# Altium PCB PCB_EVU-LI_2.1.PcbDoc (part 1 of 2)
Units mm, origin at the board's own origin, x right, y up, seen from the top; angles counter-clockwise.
Board outline 33.02 x 17.78 mm, 4 copper layers (Top, Int_1, Int_2, Bot), stack 1.546 mm thick; 75 components, 60 nets, 297 pads, 132 vias.
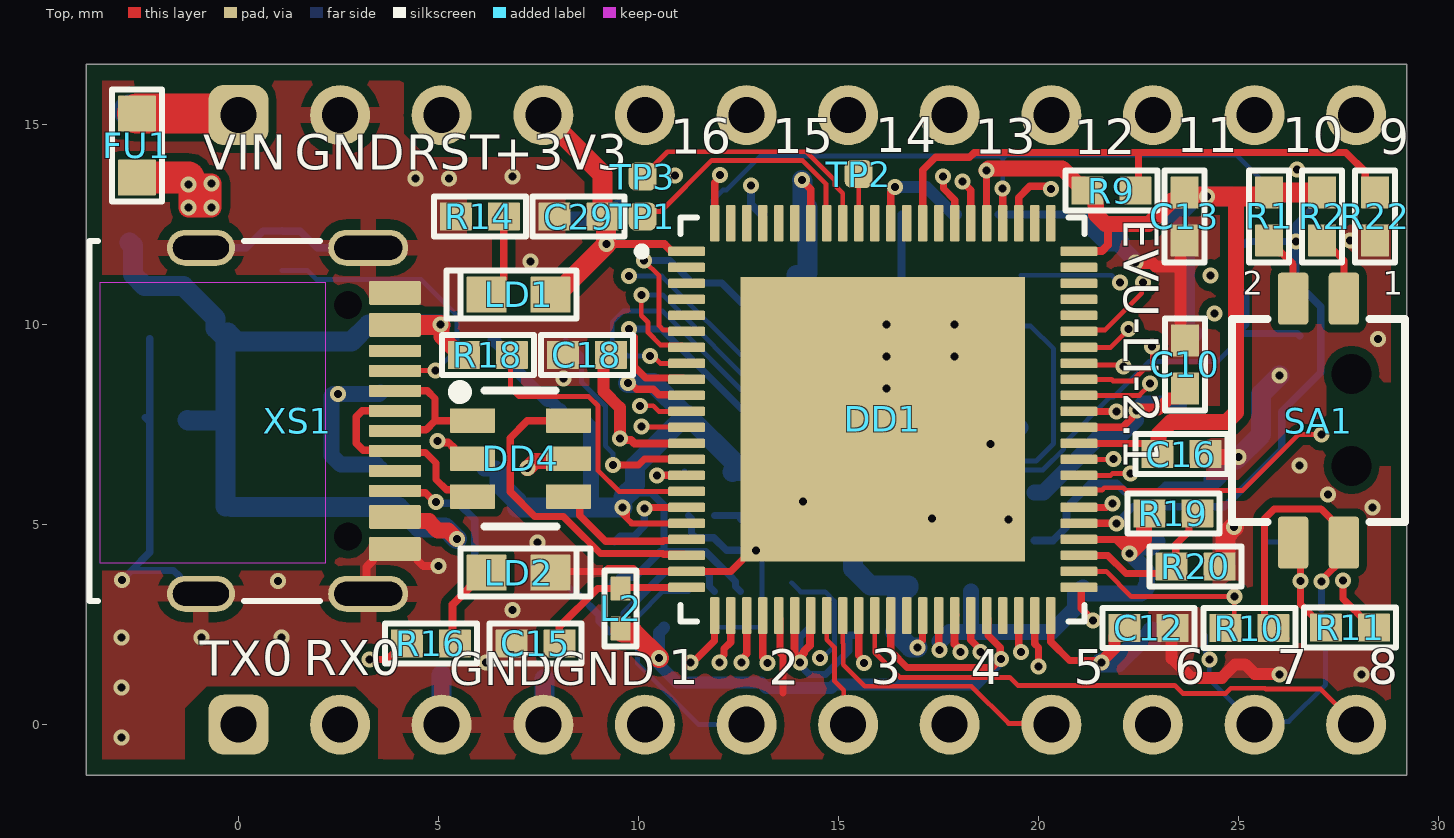
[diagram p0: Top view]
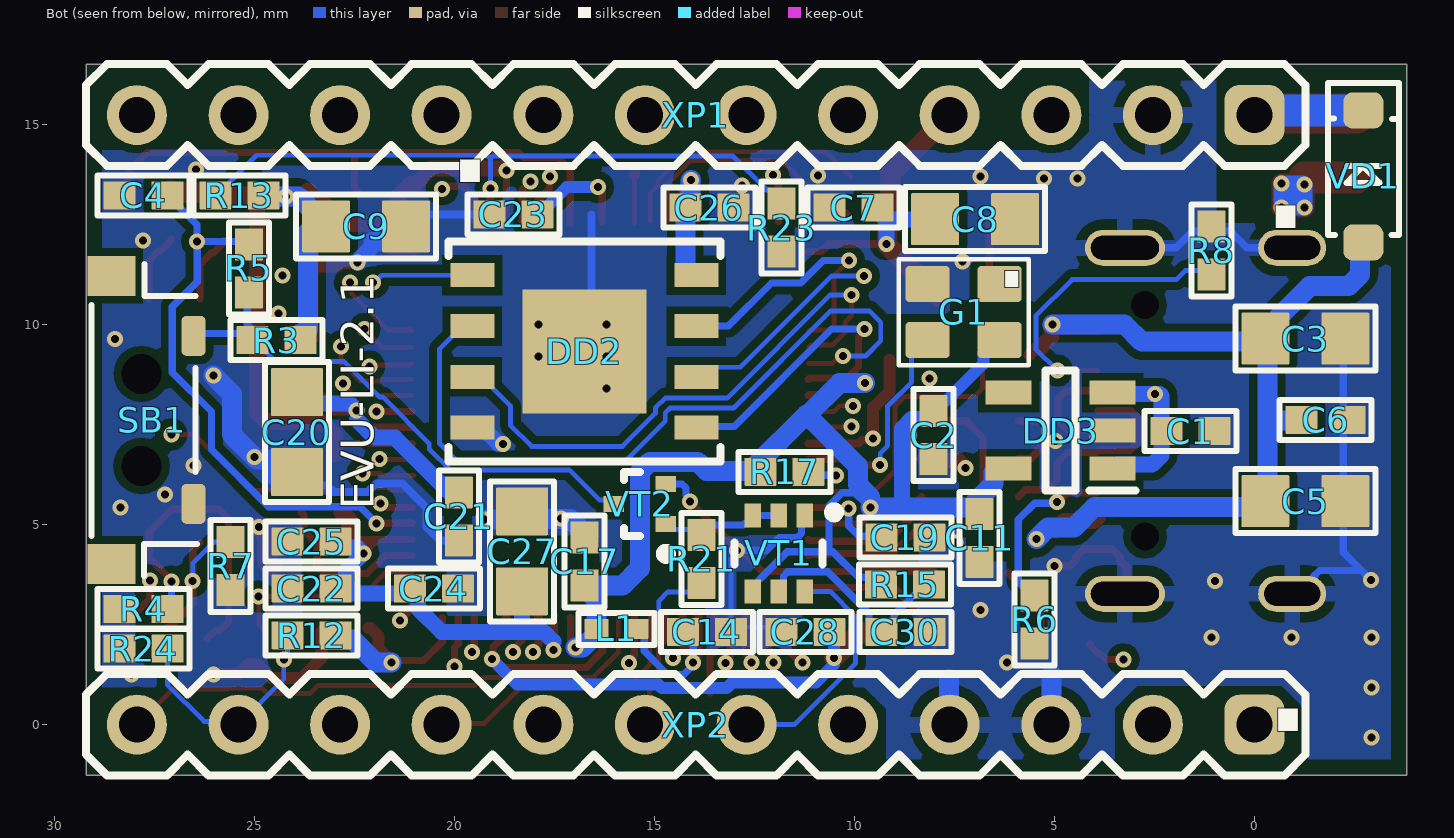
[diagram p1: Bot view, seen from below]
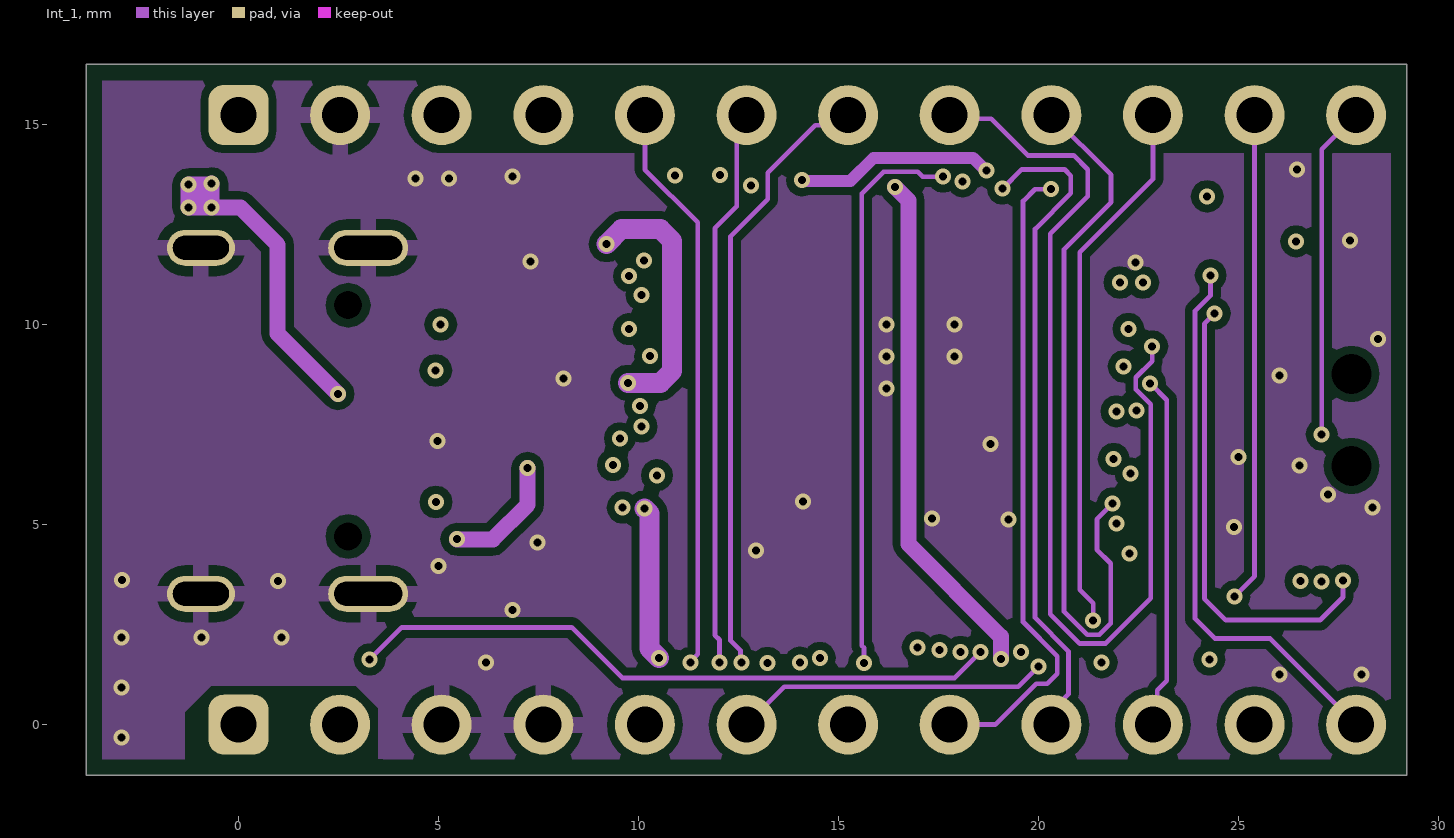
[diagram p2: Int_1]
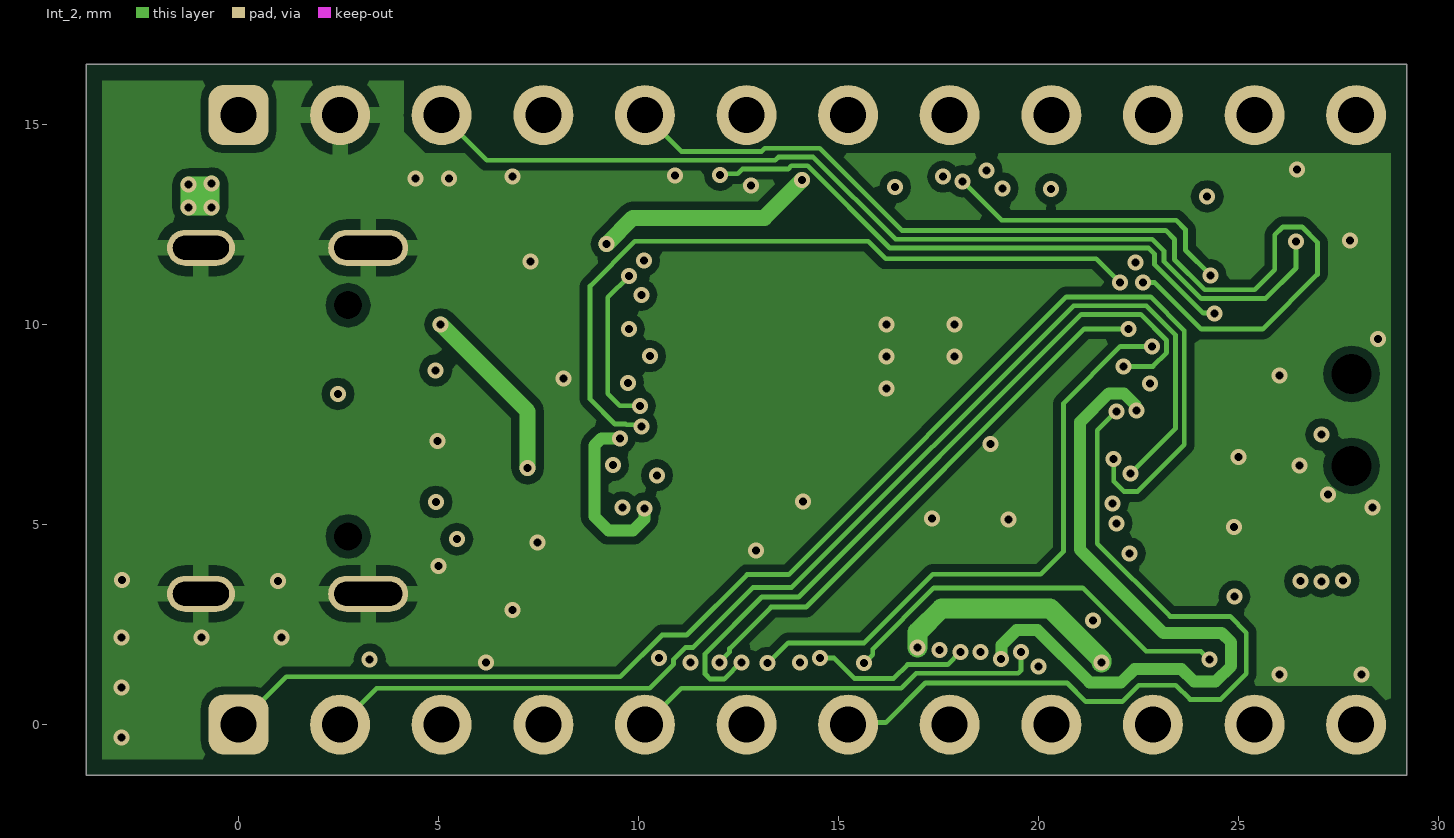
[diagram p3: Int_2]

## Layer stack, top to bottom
Top Solder: solder mask 0.01, Solder Resist, Dk 3.5
Top: signal copper 0.035
Prepreg_T: prepreg 0.138, TG-150, Dk 4.2
Int_1: signal copper 0.018
Core: core 1.164, TG-150, Dk 4.6
Int_2: signal copper 0.018
Prepreg_B: prepreg 0.138, TG-150, Dk 4.2
Bot: signal copper 0.035
Bottom Solder: solder mask 0.01, Solder Resist, Dk 3.5

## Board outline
-3.81,-1.27 -3.81,16.51 29.21,16.51 29.21,-1.27

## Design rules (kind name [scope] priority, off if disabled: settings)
AssemblyTestPointUsage [All] p1 off:
AssemblyTestpoint [All] p1 off: testpointundercomponent=TRUE minsize=1.016 maxsize=2.54 preferedsize=1.524 minholesize=0 maxholesize=1.016 preferedholesize=0.813 testpointgrid=0.025 usegrid=TRUE gridtolerance=0 allowsidetop=TRUE allowsidebottom=TRUE
BoardOutlineClearance [All] p1: gap=0.4 ignorepadtopadclearanceinfootprint=FALSE except(0: Arc-SplitContinuation Track-SplitContinuation SMDPad-SplitContinuation THPad-SplitContinuation Via-SplitContinuation Fill-SplitContinuation Poly-SplitContinuation Region-SplitContinuation Text-SplitContinuation)
Clearance Clearance_board_edge [OnLayer('Keep-Out Layer')] p1: gap=0.2 ignorepadtopadclearanceinfootprint=FALSE
Clearance Clearance_Poly_to_Poly [InPolygon vs InPolygon] p2: gap=0.4 ignorepadtopadclearanceinfootprint=FALSE except(0: Arc-Hole Track-Hole SMDPad-Hole THPad-Hole Via-Hole Fill-Hole Poly-Hole Region-Hole Text-Hole)
Clearance Clearance_Polygon [InPolygon] p3: gap=0.2 ignorepadtopadclearanceinfootprint=FALSE except(0: Text-Hole)
Clearance Clearance_Int_layer [OnLayer('Int_layer_1') or OnLayer('Int_layer_2')] p4: gap=0.2 ignorepadtopadclearanceinfootprint=FALSE except(0: Text-Hole)
Clearance [All] p5: gap=0.1 ignorepadtopadclearanceinfootprint=FALSE
ComponentClearance [All] p1 off: gap=0 collisioncheckmode=3 verticalgap=1 showdistances=FALSE
DiffPairsRouting DiffPairs_100 [InDifferentialPairClass('100 Ohm')] p1: maxlimit=0.18 minlimit=0.13 mostfreqgap=0.18 toplayer_maxgap=0.13 toplayer_prefgap=0.13 toplayer_minwidth=0.14 toplayer_maxwidth=0.14 toplayer_prefwidth=0.14 bottomlayer_maxgap=0.13 bottomlayer_prefgap=0.13 bottomlayer_minwidth=0.14 bottomlayer_maxwidth=0.14 bottomlayer_prefwidth=0.14 impedanceprofiledriven=TRUE impedanceprofileid={9381E8F4-4B66-44EE-9FF4-B1D978838FA6} impedanceprofilevalue=100.000000 maxuncoupledlength=12.7
DiffPairsRouting DiffPair_90 [InDifferentialPairClass('90 Ohm')] p2: maxlimit=0.13 minlimit=0.13 mostfreqgap=0.13 toplayer_minwidth=0.18 toplayer_maxwidth=0.18 toplayer_prefwidth=0.18 midlayer1_minwidth=0.11 midlayer1_maxwidth=0.11 midlayer1_prefwidth=0.11 midlayer2_minwidth=0.11 midlayer2_maxwidth=0.11 midlayer2_prefwidth=0.11 bottomlayer_minwidth=0.18 bottomlayer_maxwidth=0.18 bottomlayer_prefwidth=0.18 impedanceprofiledriven=TRUE impedanceprofileid={33ED77F1-C44D-40A2-8D01-BA86BD42C323} impedanceprofilevalue=90.000000 maxuncoupledlength=12.7
DiffPairsRouting [All] p3: maxlimit=0.25 minlimit=0.15 mostfreqgap=0.25 toplayer_maxgap=0.15 toplayer_prefgap=0.15 toplayer_minwidth=0.15 toplayer_maxwidth=0.3 toplayer_prefwidth=0.3 midlayer1_mingap=0.2 midlayer1_minwidth=0.2 midlayer1_maxwidth=0.2 midlayer1_prefwidth=0.2 midlayer2_mingap=0.25 midlayer2_minwidth=0.25 midlayer2_maxwidth=0.25 midlayer2_prefwidth=0.25 bottomlayer_maxgap=0.15 bottomlayer_prefgap=0.15 bottomlayer_minwidth=0.15 bottomlayer_maxwidth=0.3 bottomlayer_prefwidth=0.3 maxuncoupledlength=12.7
FabricationTestPointUsage [All] p1 off: valid=0 allowmultiple=FALSE
FabricationTestpoint [All] p1 off: side=3 testpointundercomponent=TRUE minsize=1.016 maxsize=2.54 preferedsize=1.524 minholesize=0 maxholesize=1.016 preferedholesize=0.813 testpointgrid=0.025 allowsidetop=TRUE allowsidebottom=TRUE usegrid=TRUE gridtolerance=0
FanoutControl Fanout_BGA [IsBGA] p1 off: bgadir=Out bgaviamode=Centered fanoutstyle=Auto fanoutdirection=Alternating viagrid=0.025 // Fanout_BGA (Default Rule)
FanoutControl Fanout_LCC [IsLCC] p2 off: bgadir=Out bgaviamode=Centered fanoutstyle=Auto fanoutdirection=Alternating viagrid=0.025 // Fanout_LCC (Default Rule)
FanoutControl Fanout_SOIC [IsSOIC] p3 off: bgadir=Out bgaviamode=Centered fanoutstyle=Auto fanoutdirection=Alternating viagrid=0.025 // Fanout_SOIC (Default Rule)
FanoutControl Fanout_Small [(CompPinCount < 5)] p4 off: bgadir=Out bgaviamode=Centered fanoutstyle=Auto fanoutdirection=OutThenIn viagrid=0.025 // Fanout_Small (Default Rule)
FanoutControl Fanout_Default [All] p5 off: bgadir=Out bgaviamode=Centered fanoutstyle=Auto fanoutdirection=Alternating viagrid=0.025 // Fanout_Default (Default Rule)
Height [All] p1 off: minheight=0.2 maxheight=16 prefheight=16
HoleSize [All] p1 off: absolutevalues=TRUE maxlimit=9 minlimit=0.3 maxpercent=80.000 minpercent=20.000
HoleToHoleClearance [All] p1: gap=0.5 allowstackedmicrovias=TRUE
Length [InNetClass('CSI')] p1: maxlimit=24.1 minlimit=22.1
MatchedLengths USB1c [InNetClass('USB1_c')] p1: tolerance=25.4 checknetsindiffpair=FALSE checkdiffpairvsdiffpair=TRUE checkxsignals=TRUE checkothers=TRUE usedelayunits=TRUE delaytolerance=10.000000
MatchedLengths USB0c [InNetClass('USB0_c')] p2: tolerance=25.4 checknetsindiffpair=FALSE checkdiffpairvsdiffpair=TRUE checkxsignals=TRUE checkothers=TRUE usedelayunits=TRUE delaytolerance=10.000000
MatchedLengths I2S1 [InxSignalClass('I2S1')] p3: tolerance=25.4 checknetsindiffpair=FALSE checkdiffpairvsdiffpair=TRUE checkxsignals=TRUE checkothers=TRUE usedelayunits=TRUE delaytolerance=10.000000
MatchedLengths I2S0 [InxSignalClass('I2S0')] p4: tolerance=25.4 checknetsindiffpair=FALSE checkdiffpairvsdiffpair=TRUE checkxsignals=TRUE checkothers=TRUE usedelayunits=TRUE delaytolerance=10.000000
MatchedLengths DP [InxSignalClass('DP')] p5: tolerance=25.4 checknetsindiffpair=FALSE checkdiffpairvsdiffpair=TRUE checkxsignals=TRUE checkothers=TRUE usedelayunits=TRUE delaytolerance=10.000000
MatchedLengths USB1 [InxSignalClass('USB1')] p6: tolerance=25.4 checknetsindiffpair=FALSE checkdiffpairvsdiffpair=TRUE checkxsignals=TRUE checkothers=TRUE usedelayunits=TRUE delaytolerance=10.000000
MatchedLengths USB0 [InxSignalClass('USB0')] p7: tolerance=25.4 checknetsindiffpair=FALSE checkdiffpairvsdiffpair=TRUE checkxsignals=TRUE checkothers=TRUE usedelayunits=TRUE delaytolerance=10.000000
MinimumSolderMaskSliver MinimumSolderMaskSliver_TQFP [InComponentClass('TQFP_MSK_SL_0.1')] p1: minsoldermaskwidth=0.1
MinimumSolderMaskSliver [All] p2: minsoldermaskwidth=0.15
PlaneClearance [All] p1: clearance=0.4
PlaneConnect PlaneConnect_Direct [InComponentClass('Mount_DirConn')] p1: planeconnectstyle=Direct reliefexpansion=0.508 reliefentries=4 reliefconductorwidth=0.254 reliefairgap=0.254
PlaneConnect PlaneConnect_VIA [IsVia] p2: planeconnectstyle=Direct reliefexpansion=0.508 reliefentries=4 reliefconductorwidth=0.254 reliefairgap=0.254
PlaneConnect [All] p3: planeconnectstyle=Relief reliefexpansion=0.3 reliefentries=4 reliefconductorwidth=0.5 reliefairgap=0.3
PolygonConnect PolygonConnect_DIRECT [IsPadHoleValid vs IsPolygon] p1: connectstyle=Relief reliefconductorwidth=0.4 reliefentries=4 polygonreliefangle="90 Angle" airgapwidth=0.254
PolygonConnect PolygonCON_VIA [IsVia vs IsPolygon] p2: connectstyle=Direct reliefconductorwidth=0.254 reliefentries=4 polygonreliefangle="90 Angle" airgapwidth=0.254
PolygonConnect [All] p3: connectstyle=Direct reliefconductorwidth=0.5 reliefentries=4 polygonreliefangle="90 Angle" airgapwidth=0.2
RoutingCorners [All] p1: cornerstyle=45-Degree minsetback=2.5 maxsetback=2.5
RoutingVias [All] p1: holewidth=0.3 width=0.7 viastyle="Through Hole" minholewidth=0.2 minwidth=0.4 maxholewidth=0.5 maxwidth=1.2
SilkToSilkClearance [All] p1 off: silktosilkclearance=0
SilkToSolderMaskClearance SilkscreenOverComponentPads [IsPad] p1 off: minsilkscreentomaskgap=0.2 clearancetoexposedcopper=TRUE
SolderMaskExpansion SolderMaskExpansion_via [IsVia] p1: expansion=-0.8 istentingtop=FALSE
SolderMaskExpansion [All] p2: expansion=0.075 istentingtop=FALSE
Width Width_50 [InNetClass('S50')] p1: maxlimit=0.2 minlimit=0.14 preferedwidth=0.2 toplayer_minwidth=0.2 bottomlayer_minwidth=0.2 impedanceprofiledriven=TRUE impedanceprofileid={09F03C0F-4992-4264-92D2-5678F8C1E202} impedanceprofilevalue=50.000000 minimp=50.000000 maximp=50.000000 favimp=50.000000
Width Width_PWR [InNetClass('PWR')] p2: maxlimit=2 minlimit=0.2 preferedwidth=0.7 midlayer2_maxwidth=1.5 minimp=50.000000 maximp=50.000000 favimp=50.000000
Width [All] p3: maxlimit=1 minlimit=0.12 preferedwidth=0.3 minimp=50.000000 maximp=50.000000 favimp=50.000000
10 further rules are at their usual default settings.

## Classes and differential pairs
differential pair class "90 Ohm": USB
differential pair USB: +USB_p -USB_n

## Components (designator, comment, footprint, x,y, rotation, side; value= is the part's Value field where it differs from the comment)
C1 "GRM155R71C104KA88D" CAPC1005X50N 1.605,7.337 r0 bottom value=100nF
C2 "GRM155R71C104KA88D" CAPC1005X50N 8.021,7.235 r90 bottom value=100nF
C3 "GRM21BR61C106KE15L" CAPC2012X125N -1.27,9.652 r0 bottom value=10uF
C4 "GRM155R71C104KA88D" CAPC1005X50N 27.777,13.234 r180 bottom value=100nF
C5 "GRM21BR61C106KE15L" CAPC2012X125N -1.27,5.588 r0 bottom value=10uF
C6 "GRM155R71C104KA88D" CAPC1005X50N -1.778,7.62 r0 bottom value=100nF
C7 "GRM155R71C104KA88D" CAPC1005X50N 10.022,12.928 r180 bottom value=100nF
C8 "GRM21BR61C106KE15L" CAPC2012X125N 6.984,12.637 r0 bottom value=10uF
C9 "GRM21BR61C106KE15L" CAPC2012X125N 22.212,12.458 r0 bottom value=10uF
C10 "GRM155R71C104KA88D" CAPC1005X50N 23.668,9.004 r270 top value=100nF
C11 "GRM155R71C104KA88D" CAPC1005X50N 6.87,4.672 r90 bottom value=100nF
C12 "GRM155R71C104KA88D" CAPC1005X50N 22.754,2.422 r180 top value=100nF
C13 "GRM155R71C104KA88D" CAPC1005X50N 23.655,12.705 r90 top value=100nF
C14 "GRM155R71C104KA88D" CAPC1005X50N 13.69,2.32 r0 bottom value=100nF
C15 "GRM155R71C104KA88D" CAPC1005X50N 7.43,2.029 r0 top value=100nF
C16 "GRM155R71C104KA88D" CAPC1005X50N 23.57,6.764 r180 top value=100nF
C17 "GRM155R71C104KA88D" CAPC1005X50N 16.747,4.079 r270 bottom value=100nF
C18 "GRM155R71C104KA88D" CAPC1005X50N 8.708,9.244 r0 top value=100nF
C19 "GRM155R71C104KA88D" CAPC1005X50N 8.727,4.68 r0 bottom value=100nF
C20 "GRM21BR61C106KE15L" CAPC2012X125N 23.939,7.316 r90 bottom value=10uF
C21 "GRM155R71C104KA88D" CAPC1005X50N 19.894,5.209 r90 bottom value=100nF
C22 "GRM155R71C104KA88D" CAPC1005X50N 23.571,3.4 r180 bottom value=100nF
C23 "GRM155R71C104KA88D" CAPC1005X50N 18.531,12.754 r180 bottom value=100nF
C24 "GRM155R71C104KA88D" CAPC1005X50N 20.515,3.4 r0 bottom value=100nF
C25 "GRM155R71C104KA88D" CAPC1005X50N 23.571,4.576 r180 bottom value=100nF
C26 "GRM155R71C104KA88D" CAPC1005X50N 13.63,12.928 r0 bottom value=100nF
C27 "GRM21BR61C106KE15L" CAPC2012X125N 18.311,4.332 r270 bottom value=10uF
C28 "GRM155R71C104KA88D" CAPC1005X50N 11.231,2.32 r180 bottom value=100nF
C29 "GRM155R71C104KA88D" CAPC1005X50N 8.5,12.7 r0 top value=100nF
C30 "GRM155Z71A105KE01D" CAPC1005X50N 8.727,2.32 r180 bottom value=1uF
DD1 "BE-U1000" QFNWB10X10-88L-AL 16.105,7.63 r0 top
DD2 "MT25QL128ABA1EW7-0SIT" W-PDFN-8(5x6) 16.755,9.33 r180 bottom
DD3 "AP2112K-3.3TRG1" SOT95P285X140-5N 4.847,7.349 r0 bottom
DD4 "USBLC6-2SC6" SOT95P280X145-6N 7.05,6.65 r0 top
FU1 "JFC0603-0500FS" RESC1608X45N -2.54,14.478 r270 top value=500mA
G1 "OT252025MJBA4SL" Crystal_4-SMD_2.5x2.0 7.274,10.316 r0 bottom
L1 "BLM15AX601SN1" BLM15X10X05X50N 15.955,2.397 r180 bottom value="600 Ом/100MГц 0,5A 0,34 Ом"
L2 "BLM15AX601SN1" BLM15X10X05X50N 9.555,2.905 r90 top value="600 Ом/100MГц 0,5A 0,34 Ом"
LD1 "KPT-1608PWF-A" KPT1608X16X08X75N_LINE 7,10.75 r180 top
LD2 "KPT-1608SGC" KPT1608X16X08X75N_LINE 7,3.8 r0 top
R1 "RC0402FR-071KL" RESC1005X35N 25.767,12.705 r270 top value=1K
R2 "RC0402FR-071KL" RESC1005X35N 27.089,12.705 r270 top value=1K
R3 "RC0402FR-0710KL" RESC1005X35N 24.453,9.61 r180 bottom value=10K
R4 "RC0402FR-07100KL" RESC1005X35N 27.777,2.89 r180 bottom value=100K
R5 "RC0402FR-071KL" RESC1005X35N 25.142,11.407 r90 bottom value=1K
R6 "RC0402FR-0710KL" RESC1005X35N 5.505,2.63 r270 bottom value=10K
R7 "RC0402FR-07100KL" RESC1005X35N 25.6,3.965 r90 bottom value=100K
R8 "RC0402FR-0710KL" RESC1005X35N 1.08,11.855 r90 bottom value=10K
R9 "RC0402FR-0710KL" RESC1005X35N 21.823,13.35 r0 top value=10K
R10 "RC0402FR-0710KL" RESC1005X35N 25.273,2.413 r180 top value=10K
R11 "RC0402FR-0710KL" RESC1005X35N 27.789,2.422 r0 top value=10K
R12 "RC0402FR-0710KL" RESC1005X35N 23.571,2.235 r0 bottom value=10K
R13 "RC0402FR-0710KL" RESC1005X35N 25.376,13.234 r180 bottom value=10K
R14 "CR0402-JW-202-G" RESC1005X35N 6.032,12.7 r180 top value=2K
R15 "RC0402FR-0710KL" RESC1005X35N 8.739,3.5 r180 bottom value=10K
R16 "CR0402-JW-331-G" RESC1005X35N 4.807,2.029 r180 top value=330R
R17 "RC0402FR-0710KL" RESC1005X35N 11.75,6.318 r180 bottom value=10K
R18 "RC0402FR-070RL" RESC1005X35N 6.231,9.244 r0 top value=0R
R19 "RC0402FR-0791RL" RESC1005X35N 23.37,5.281 r180 top value=91R
R20 "RC0402FR-07130RL" RESC1005X35N 23.93,3.955 r0 top value=130R
R21 "RC0402FR-071KL" RESC1005X35N 13.825,4.146 r90 bottom value=1K
R22 "RC0402FR-07100KL" RESC1005X35N 28.412,12.705 r90 top value=100K
R23 "RC0402FR-07100KL" RESC1005X35N 11.825,12.428 r90 bottom value=100K
R24 "RC0402FR-07100KL" RESC1005X35N 27.777,1.9 r180 bottom value=100K
SA1 "DHN-02-V-T/R" A6H-21 27,7.6 r180 top
SB1 "KLS7-TS3606-3.5-180" KLS7-TS3606-3.5-180 27.178,7.62 r90 bottom
TP1 "" PIN_0.7x0.7#1 11.203,18.114 r90 top
TP2 "" PIN_0.7x0.7#2 16.106,13.798 r90 top
TP3 "" PIN_0.7x0.7#3 13.707,18.265 r90 top
VD1 "1N5817W" DIOD_SOD-123 -2.72,13.705 r90 bottom
VT1 "BSS8402DW-7-F" FP-SOT363-MFG 11.897,4.28 r270 bottom
VT2 "DMG1012T-7" DIOD-SOT523-3_V 15.368,5.519 r0 bottom
XP1 "DS1021-1x12" PLS-12 0,15.24 r0 bottom locked
XP2 "DS1021-1x12" PLS-12 0,0 r0 bottom locked
XS1 "TYPE-C-31-M-12" TYPE-C-31-M-12 3.81,10.795 r270 top locked

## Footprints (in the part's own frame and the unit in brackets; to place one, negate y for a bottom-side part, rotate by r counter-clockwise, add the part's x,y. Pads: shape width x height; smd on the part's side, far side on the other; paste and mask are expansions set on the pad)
A6H-21 [mm] "SWITCH SMT 2-WAY"
  rrect22% 0.76x1.3 smd: 1(-0.635,-3.048) 2(0.635,-3.048) 11(-0.635,3.048) 22(0.635,3.048)
  silkscreen extent -2.16,-2.54 2.16,2.54, body extent -1.89,-3.35 1.89,3.35, height 1.55
BLM15X10X05X50N [mm]
  rrect5% 0.6x0.5 smd mask+0.07: 1(-0.5,0) 2(0.5,0)
  silkscreen extent -0.95,-0.4 0.95,0.4, body extent -0.5,-0.25 0.5,0.25, height 0.5
CAPC1005X50N [mm]
  rrect5% 0.8x0.7 smd paste-25.4 mask+0.07: 1(-0.6,0) 2(0.6,0)
  silkscreen extent -1.15,-0.5 1.15,0.5, body extent -0.57,-0.27 0.58,0.28, height 0.55
CAPC2012X125N [mm] "SMD Ceramic Chip Capacitor 0805,  metric 2012"
  rrect5% 1.2x1.3 smd mask+0.07: 1(-1,0) 2(1,0)
  silkscreen extent -1.75,-0.8 1.75,0.8, body extent -1.05,-0.65 1.05,0.65, height 1.25
Crystal_4-SMD_2.5x2.0 [mm]
  rrect20% 1.1x0.9 smd mask+0.075: 1(-0.9,-0.7) 2(0.9,-0.7) 3(0.9,0.7) 4(-0.9,0.7)
  silkscreen extent -1.63,-1.32 1.62,1.33, body extent -1.3,-1.05 1.3,1.05, height 0.7
DIOD-SOT523-3_V [mm] "SOT523, 3-Leads, Body 1.6x0.8mm, Pitch 0.50mm"
  rect 0.51x0.4 smd: 1(-0.65,0.5) 2(-0.65,-0.5) 3(0.65,0)
  silkscreen extent -0.77,-0.8 0.4,1.37, body extent -0.4,-0.8 0.4,0.8, height 0.86
DIOD_SOD-123 [mm]
  rrect50% 0.9x1 smd: A(-1.65,0) C(1.65,0)
  silkscreen extent -1.46,-0.89 2.34,0.88, body extent -1.85,-0.8 1.85,0.8, height 1.27
FP-SOT363-MFG [mm]
  rect 0.6x0.42 smd paste+0 mask+0: 1(-0.95,0.65) 2(-0.95,0) 3(-0.95,-0.65) 4(0.95,-0.65) 5(0.95,0) 6(0.95,0.65)
  silkscreen extent -1.15,-1.1 0.28,1.51, body extent -1.05,-1.07 1.05,1.07, height 1.1
KLS7-TS3606-3.5-180 [mm] "Tact Switch 3x6"
  rrect40% 1x0.6 smd: 1(-2.1,-0.65) 2(2.1,-0.65)
  round 0 hole 1: 10(-1.15,0.65) 10(1.15,0.65)
  rect 1x1.2 smd: mnt(-3.6,1.4) mnt(3.6,1.4)
  silkscreen extent -3.9,-0.74 3.9,1.9, body extent -3.9,-0.75 3.9,2.85, height 3.5
KPT1608X16X08X75N_LINE [mm]
  rrect5% 1x0.9 smd mask+0.07: 1(-0.8,0) 2(0.8,0)
  silkscreen extent -1.45,-0.6 1.8,0.6, body extent -0.8,-0.4 0.8,0.4, height 0.76
PIN_0.7x0.7#1 [mm]
  rrect50% 0.7x0.7 smd paste-2: 1(-5.414,1.103)
PIN_0.7x0.7#2 [mm]
  rrect50% 0.7x0.7 smd paste-2: 1(-0.035,0.605)
PIN_0.7x0.7#3 [mm]
  rrect50% 0.7x0.7 smd paste-2: 1(-4.565,3.607)
PLS-12 [mm] "Pin Header, 2.54mm pitch"
  rrect50% 1.5x1.5 hole 0.9: 1(0,0)
  round 1.5 hole 0.9: 2(2.54,0) 3(5.08,0) 4(7.62,0) 5(10.16,0) 6(12.7,0) 7(15.24,0) 8(17.78,0) 9(20.32,0) 10(22.86,0) 11(25.4,0) 12(27.94,0)
  silkscreen extent -1.27,-1.27 29.21,1.27, body extent -1.27,-1.27 29.21,1.27, height 8.49
QFNWB10X10-88L-AL [mm]
  rrect25% 0.92x0.24 smd: 1(-4.905,4.2) 2(-4.905,3.8) 3(-4.905,3.4) 4(-4.905,3) 5(-4.905,2.6) 6(-4.905,2.2) 7(-4.905,1.8) 8(-4.905,1.4) 9(-4.905,1) 10(-4.905,0.6) 11(-4.905,0.2) 12(-4.905,-0.2) 13(-4.905,-0.6) 14(-4.905,-1) 15(-4.905,-1.4) 16(-4.905,-1.8) 17(-4.905,-2.2) 18(-4.905,-2.6) 19(-4.905,-3) 20(-4.905,-3.4) 21(-4.905,-3.8) 22(-4.905,-4.2) 45(4.905,-4.2) 46(4.905,-3.8) 47(4.905,-3.4) 48(4.905,-3) 49(4.905,-2.6) 50(4.905,-2.2) 51(4.905,-1.8) 52(4.905,-1.4) 53(4.905,-1) 54(4.905,-0.6) 55(4.905,-0.2) 56(4.905,0.2) 57(4.905,0.6) 58(4.905,1) 59(4.905,1.4) 60(4.905,1.8) 61(4.905,2.2) 62(4.905,2.6) 63(4.905,3) 64(4.905,3.4) 65(4.905,3.8) 66(4.905,4.2)
  rrect25% 0.24x0.92 smd: 23(-4.2,-4.905) 24(-3.8,-4.905) 25(-3.4,-4.905) 26(-3,-4.905) 27(-2.6,-4.905) 28(-2.2,-4.905) 29(-1.8,-4.905) 30(-1.4,-4.905) 31(-1,-4.905) 32(-0.6,-4.905) 33(-0.2,-4.905) 34(0.2,-4.905) 35(0.6,-4.905) 36(1,-4.905) 37(1.4,-4.905) 38(1.8,-4.905) 39(2.2,-4.905) 40(2.6,-4.905) 41(3,-4.905) 42(3.4,-4.905) 43(3.8,-4.905) 44(4.2,-4.905) 67(4.2,4.905) 68(3.8,4.905) 69(3.4,4.905) 70(3,4.905) 71(2.6,4.905) 72(2.2,4.905) 73(1.8,4.905) 74(1.4,4.905) 75(1,4.905) 76(0.6,4.905) 77(0.2,4.905) 78(-0.2,4.905) 79(-0.6,4.905) 80(-1,4.905) 81(-1.4,4.905) 82(-1.8,4.905) 83(-2.2,4.905) 84(-2.6,4.905) 85(-3,4.905) 86(-3.4,4.905) 87(-3.8,4.905) 88(-4.2,4.905)
  rect 7.112x7.112 smd paste-3: 89(0,0)
  silkscreen extent -6.12,-5.05 5.05,5.05, body extent -5,-5 5,5, height 0.85
RESC1005X35N [mm]
  rrect5% 0.8x0.7 smd paste-25.4 mask+0.07: 1(-0.6,0) 2(0.6,0)
  silkscreen extent -1.15,-0.5 1.15,0.5, body extent -0.55,-0.27 0.55,0.28, height 0.4
RESC1608X45N [mm]
  rrect5% 0.9x0.95 smd mask+0.07: 1(-0.8,0) 2(0.8,0)
  silkscreen extent -1.4,-0.63 1.4,0.63, body extent -0.85,-0.45 0.85,0.45, height 0.55
SOT95P280X145-6N [mm]
  rrect5% 1.12x0.61 smd mask+0.05: 1(-1.2,0.95) 2(-1.2,0) 3(-1.2,-0.95) 4(1.2,-0.95) 5(1.2,0) 6(1.2,0.95)
  silkscreen extent -1.66,-1.7 0.9,1.81, body extent -1.42,-1.55 1.42,1.55, height 1.46
SOT95P285X140-5N [mm]
  rect 1.15x0.6 smd: 1(-1.3,0.95) 2(-1.3,0) 3(-1.3,-0.95) 4(1.3,-0.95) 5(1.3,0.95)
  silkscreen extent -1.88,-1.5 0.38,1.5, body extent -1.43,-1.5 1.43,1.5, height 1.4
TYPE-C-31-M-12 [mm] "USB TYPE-C 5A 16P Female SMD USB Connectors"
  rrect15% 0.6x1.3 smd mask+0.05: A1_B12(0,0.1) A4_B9(0.8,0.1) B1_A12(6.4,0.1) B4_A9(5.6,0.1)
  rrect15% 0.3x1.3 smd mask+0.05: A5(1.95,0.1) A6(2.95,0.1) A7(3.45,0.1) A8(4.45,0.1) B5(4.95,0.1) B6(3.95,0.1) B7(2.45,0.1) B8(1.45,0.1)
  oval 0.9x2 hole 0.6 slot 1.7 at 90 deg mask+0.05: S1(-1.125,-0.57) S3(7.525,-0.57)
  oval 0.9x1.7 hole 0.6 slot 1.4 at 90 deg mask+0.05: S2(-1.125,-4.75) S4(7.525,-4.75)
  round 0 hole 0.7 unplated: ""(0.31,-1.07) ""(6.09,-1.07)
  Top keep-out region: -0.25,-7.275 6.75,-7.275 6.75,-1.625 -0.25,-1.625
  silkscreen extent -1.3,-7.53 7.7,-1.78, body extent -1.27,-7.35 7.68,0.55, height 3.16
W-PDFN-8(5x6) [mm]
  rect 1.1x0.6 smd mask+0.05: 1(-2.8,1.905) 2(-2.8,0.635) 3(-2.8,-0.635) 4(-2.8,-1.905) 5(2.8,-1.905) 6(2.8,-0.635) 7(2.8,0.635) 8(2.8,1.905)
  rect 3.1x3.1 smd mask+0.05: EP(0,0)
  silkscreen extent -3.4,-2.75 3.4,2.75, body extent -3.06,-2.51 3.04,2.49, height 0.95

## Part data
C1 C2 C4 C6 C7 C10 C11 C12 C13 C14 C15 C16 C17 C18 C19 C21 C22 C23 C24 C25 C26 C28 C29: "0402 X7R  0,1 uF±10% 16V", Manufacturer="\"Murata\"", Power_Voltage=16В, Tolerance=±10%, Value Ru="0,1 мкФ"
C3 C5 C8 C9 C20 C27: "0805 X5R 10uF±10% 16V", Manufacturer="\"Murata\"", Power_Voltage=16V, Tolerance=±10%, Value Ru="10 мкФ"
C30: "0402 X7R  1 uF±10% 10V", Manufacturer="\"Murata\"", Power_Voltage=10В, Tolerance=±10%, Value Ru="1 мкФ"
DD1: "Microcontroller BE-U1000", Manufacturer="\"Baikal Electronics\"", Package=None
DD2: "FLASH 128MBIT SPI 8WPDFN", Arrow Part Number="MT25QL128ABA1ESE-0SIT TR", Manufacturer="\"Micron\"", Mouser Part Number=340-224871-REEL
DD3: "LDO voltage regulator", Manufacturer="\"Diodes\"", Manufacturer_Name="Diodes Incorporated", Mouser Part Number=621-AP2112K-3.3TRG1
DD4: "Very low capacitance ESD protector", Manufacturer="\"STMicroelectronics\""
FU1: "Fuse 500mA 32V 0603", Manufacturer="\"JDT Fuse Industrial\""
G1: "3.3V ±10ppm 5mA ±20ppm CMOS 25MHz  Oscillator", Manufacturer="\"YXC\"", Manufacturer_Part_Number=OT322525MJBA4SL
L1 L2: "600 Ohms/100MHz 0,5A 0,34 Ohms", Manufacturer="\"Murata\""
LD1: "0603 LED Diod SMD White", Manufacturer="\"Kingbright\""
LD2: "0603 LED Diod SMD Green", Manufacturer="\"Kingbright\""
R1 R2 R5 R21: "0402 1 kOhm ±1% 0.063W", Manufacturer="\"Yageo\"", Power_Voltage="0,0625 W", Tolerance=±1%, Value Ru="1 кОм"
R3 R6 R8 R9 R10 R11 R12 R13 R15 R17: "0402 10 kOhm ±1% 0.063W", Manufacturer="\"Yageo\"", Power_Voltage="0,0625 W", Tolerance=±1%, Value Ru="10 кОм"
R4 R7 R22 R23 R24: "0402 100 kOhm ±1% 0.063W", Manufacturer="\"Yageo\"", Power_Voltage="0,0625 W", Tolerance=±1%, Value Ru="100 кОм"
R14: "0402 2 kOhm±5% 0.063W", Manufacturer="\"Bourns\"", Power_Voltage="0,0625 W", Tolerance=±5%, Value Ru="2 кОм"
R16: "0402 330 Ohm±5% 0.063W", Manufacturer="\"Bourns\"", Power_Voltage="0,0625 W", Tolerance=±5%, Value Ru="330 Ом"
R18: "0402 0 Ohm ±1% 0.063W", Manufacturer="\"Yageo\"", Power_Voltage="0,0625 W", Tolerance=±1%, Value Ru="0 Ом"
R19: "0402 91 Ohm ±1% 0.063W", Manufacturer="\"Yageo\"", Power_Voltage="0,0625 W", Tolerance=±1%, Value Ru="91 Ом"
R20: "0402 130 Ohm ±1% 0.063W", Manufacturer="\"Yageo\"", Power_Voltage="0,0625 W", Tolerance=±1%, Value Ru="130 Ом"
SA1: "2 switches in case", Manufacturer="\"DIPTRONICS\""
SB1: "Kind of Tactile Switch", Manufacturer="\"KLS\""
TP1 TP2 TP3: library part TP, "Contacts, Test points and mounting hole pin"
VD1: "Diode Schottky 20V 1A [SOD-123]", Manufacturer="HOTTECH ELECTRONICS"
VT1: "MOSFET N/P-CH 60V/50V SC70-6", Continuous Drain Current=115/-130mA, Drain To Source Breakdown Voltage=70/-50V, Drain To Source Resistance=4.4/10Ω, Drain To Source Voltage=60/-50V, Gate To Source Voltage=20V, Manufacturer=Diodes, Max Junction Temp=+150°C, Package=SOT363, Power Dissipation=200mW, Pulse Drain Current=800mA, Temperature="-55°C to +150°C", Temperature Range Low=-55°C
VT2: "N-Channel Enhancement Mode MOSFET, 20 V, 630 mA, -55 to 150 degC, 3-Pin SOT23, RoHS, Tape and Reel", Case\/Package=SOT-523, Continuous Drain Current (ID)=630mA, Drain To Source Breakdown Voltage=20V, Drain To Source Resistance=300mOhm, Gate to Source Voltage (Vgs)=6V, Input Capacitance=60.67pF, Manufacturer="Diodes Inc", Max Operating Temperature=150degC, Max Power Dissipation=280mW, Min Operating Temperature=-55degC, On-State Resistance=400MOhm, Package Description="3-Pin Small Outline Transistor, Body 1.6 x 0.8 mm, Pitch 0.5 mm", Package Quantity=3000, Package Reference=SOT523-3, Threshold Voltage=1V
XP1 XP2: "Connector 2.54 pitch, 1 rows, 8.54 height", Manufacturer="\"Connfly\"", ManufacturerPartNumber="DS1021-1x12 (PLS-12)"
XS1: "USB TYPE-C 5A 16P Female SMD USB Connectors", Manufacturer="\"GCT\"", ManufacturerPartNumber=USB4800-03-A, Package=None

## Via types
v1: diameter 0.4, hole 0.2, Top to Bot, 132 vias

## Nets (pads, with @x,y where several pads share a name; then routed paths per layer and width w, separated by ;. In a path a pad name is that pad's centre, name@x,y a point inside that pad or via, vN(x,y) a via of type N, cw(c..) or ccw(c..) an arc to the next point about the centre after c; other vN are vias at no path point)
+1V2: C10.2 C18.2 C19.2 C20.2 C21.2 C23.2 C28.2 DD1.13 DD1.17 DD1.34 DD1.40 DD1.55 DD1.77 L2.1 | length 71.3
  Top w0.18: v1(10.155,5.405) 10.18,5.43 DD1.17@11.155,5.43 ; DD1.34@16.305,2.68 16.305,1.835 16.709,1.43 18.845,1.43 19.042,1.627 19.061,1.627 v1(19.061,1.642) ; DD1.77@16.305,12.58 16.305,13.329 v1(16.414,13.437) ; DD1.40@18.705,2.68 18.735,2.65 18.735,2.235 19.042,1.928 v1@19.042,1.661 ; DD1.55@21.055,7.43 21.06,7.435 22.1,7.435 22.336,7.671
  Top w0.2: v1(9.533,7.154) 9.571,7.116 9.814,7.116 9.9,7.03 DD1.13@11.155,7.03
  Top w0.3: C18.2@9.124,9.119 9.124,8.333 9.533,7.924 v1(9.533,7.154) ; v1(22.445,7.855) 22.464,7.874 22.988,7.874 23.268,8.154 23.467,8.154 23.668,8.354 C10.2@23.668,8.4
  Top w0.5: L2.1@9.555,2.355 9.605,2.305 9.873,2.305 v1(10.517,1.661)
  Int_1 w0.4: v1(16.414,13.437) 16.751,13.1 16.751,4.511 19.061,2.202 v1(19.061,1.642)
  Int_1 w0.5: v1(10.155,5.405) 10.28,5.28 10.28,1.898 v1(10.517,1.661)
  Int_2 w0.3: v1(9.533,7.154) 9.071,7.154 8.895,6.979 8.895,5.206 9.244,4.857 9.866,4.857 10.155,5.146 v1(10.155,5.405) ; v1(19.061,1.642) 19.08,1.662 19.08,1.99 19.455,2.364 19.971,2.364 21.279,1.056 22.068,1.056 22.402,1.39 23.572,1.39 23.882,1.08 24.43,1.08 24.814,1.464 24.814,2.057 24.58,2.292 23.121,2.292 21.038,4.374 21.038,7.561 21.759,8.282 22.132,8.282 22.426,7.988 22.426,7.874 v1(22.445,7.855)
  Bot w0.18: C19.2@9.396,4.569 9.538,4.711 9.891,4.711 10.145,4.965 10.145,5.395 v1(10.155,5.405)
  Bot w0.3: C28.2@10.642,2.427 10.517,2.302 v1(10.517,1.661) 10.517,1.499 10.966,1.05 13.064,1.05 13.2,0.914 14.814,0.914 14.9,1 18.434,1 19.061,1.627 v1(19.061,1.642) ; v1(16.414,13.437) 17.198,13.437 17.881,12.754 C23.2@17.931,12.754
  Bot w0.4: C21.2@19.894,5.809 20.127,5.809 21.492,7.174 21.994,7.174 22.441,7.621 ; v1(22.445,7.855) 22.62,8.03 23.489,8.03 C20.2@23.516,8.002
+1V7: C22.2 C24.2 C25.2 C27.2 DD1.37 DD1.48 R19.2 | length 13.4
  Top w0.18: DD1.37@17.505,2.725 17.505,1.883 v1(17.526,1.862) ; DD1.48@21.055,4.63 21.93,4.63 ; v1@22.232,4.474 22.232,4.63 ; v1(22.28,4.28) 21.93,4.63 ; 22.523,4.63 22.232,4.63 ; 21.93,4.63 22.232,4.63
  Top w0.4: v1(22.28,4.28) 22.632,4.631 22.632,5.131 22.806,5.305 R19.2@22.83,5.305
  Bot w0.3: v1(17.526,1.862) 17.526,2.072
  Bot w0.4: 17.526,2.072 17.774,2.32 18.311,2.32 ; C27.2@18.311,3.332 18.311,2.32 ; C24.2@21.115,3.4 21.065,3.4 20.915,3.25 20.915,2.91 20.326,2.32 18.311,2.32 ; C24.2@21.115,3.427 21.265,3.277 22.279,3.277 22.563,3.277 C22.2@22.713,3.427 ; C22.2@22.675,3.465 22.713,3.503 22.713,3.847 v1(22.28,4.28) 22.426,4.426 22.821,4.426 C25.2@22.971,4.576
+3V3: C2.2 C7.2 C8.2 C9.2 C11.2 C12.2 C13.2 C16.2 C17.2 C26.2 C29.2 DD1.1 DD1.10 DD1.18 DD1.36 DD1.44 DD1.54 DD1.66 DD1.71 DD1.82 DD2.8 DD3.5 G1.4 L1.1 LD1.1 R1.1 R2.1 R3.2 R9.1 R12.1 R13.2 R15.1 R17.1 VT1.4 XP1.4 | length 104.6
  Top w0.15: v1@9.533,5.328 9.71,5.15 ; v1(9.605,5.427) 9.605,5.374 v1@9.71,5.269 ; v1@9.71,5.409 v1@9.71,5.269 ; DD1.18@11.2,5.03 9.83,5.03 9.71,5.15 ; 9.71,5.15 v1@9.71,5.269
  Top w0.18: v1(9.735,8.542) 9.794,8.542 9.951,8.385 10.367,8.385 10.505,8.247 11.138,8.247 DD1.10@11.155,8.23 ; DD1.1@10.795,11.865 10.83,11.83 DD1.1@11.155,11.83 ; v1(14.082,13.61) 14.305,13.387 DD1.82@14.305,12.58 ; v1(16.98,1.93) 16.98,1.99 17.1,2.11 17.1,2.675 DD1.36@17.105,2.68 ; DD1.71@18.702,12.538 v1(18.702,13.858) ; DD1.44@20.305,2.68 20.305,2.071 20.776,1.6 v1@21.58,1.6 ; DD1.54@21.055,7.03 22.998,7.03 C16.2@22.999,7.03
  Top w0.2: C29.2@9.1,12.7 C29.2@9.188,12.612 ; v1@9.188,12.026 v1(9.201,12.013) ; v1@9.258,12.015 10.645,12.015 DD1.1@10.795,11.865 ; DD1.66@21.01,11.83 21.021,11.841 21.586,11.841 21.74,11.995 21.74,12.515
  Top w0.3: v1(21.58,1.556) 21.58,1.583 21.904,1.907 21.904,2.222 22.104,2.422 C12.2@22.154,2.422
  Top w0.4: v1(18.702,13.858) 18.751,13.907 20.591,13.907 20.998,13.5 21.123,13.5 21.423,13.2 21.423,12.985 21.443,12.966 21.443,12.749 21.677,12.515 21.74,12.515 22.752,12.515 23.342,13.105 23.505,13.105 23.655,13.255 23.655,13.298 C13.2@23.655,13.305 ; C16.2@22.998,6.764 22.998,7.03 22.998,7.247 23.317,7.567 24.7,7.567 24.935,7.801 24.935,13.198
  Top w0.5: XP1.4@7.62,15.24 8.593,14.267 9.1,13.76 C29.2@9.1,12.7 ; LD1.1@7.869,10.681 v1(9.201,12.013) ; v1@9.188,12.026 C29.2@9.188,12.612 ; C13.2@23.655,13.298 23.746,13.207 v1(24.217,13.207) 24.226,13.198 24.935,13.198 25.667,13.198 25.767,13.298 R1.1@25.767,13.305 27.044,13.305 R2.1@27.089,13.35
  Int_1 w0.3: v1(14.082,13.61) 14.102,13.59 15.296,13.59 15.877,14.171 18.362,14.171 18.675,13.858 v1(18.702,13.858)
  Int_1 w0.5: v1(9.201,12.013) 9.577,12.388 10.546,12.388 10.839,12.095 10.839,8.835 10.546,8.542 v1(9.735,8.542)
  Int_2 w0.4: v1(9.201,12.013) 9.86,12.671 13.144,12.671 v1(14.082,13.61)
  Int_2 w0.5: v1(16.98,1.93) 16.98,2.312 17.572,2.905 20.291,2.905 21.58,1.615 v1(21.58,1.556)
  Bot w0.12: R15.1@9.339,3.562 R15.1@9.339,3.612 ; 10.64,5.361 10.64,5.412
  Bot w0.18: R15.1@9.339,3.5 9.523,3.683 9.904,3.683 10.544,4.323 10.64,4.323 ; 9.765,5.567 9.993,5.795 10.316,5.795 10.64,5.471 10.64,5.412 ; 10.64,5.361 10.64,4.323 ; VT1.4@12.547,3.33 12.427,3.45 12.427,3.579 12.297,3.709 11.683,4.323 10.64,4.323
  Bot w0.3: G1.4@6.374,9.616 6.558,9.432 6.658,9.432 6.774,9.316 6.774,9.032 7.721,8.085 7.821,8.085 8.021,7.885 C2.2@8.021,7.835
  Bot w0.4: DD3.5@6.147,6.399 DD3.5@6.422,6.399 ; C11.2@6.96,5.586 6.96,5.434 C11.2@6.967,5.427 ; C8.2@7.964,12.625 C7.2@9.2,12.625 ; C2.2@8.021,7.835 8.021,7.785 8.171,7.635 8.577,7.635 8.811,7.4 8.811,5.427 ; v1(9.201,12.013) 9.201,12.624 C7.2@9.2,12.625 ; C7.2@9.5,12.925 C7.2@9.2,12.625 ; v1(9.605,5.427) 9.619,5.442 9.619,5.696
  Bot w0.5: DD3.5@6.522,6.299 6.522,6.024 C11.2@6.96,5.586 ; C11.2@6.967,5.427 8.811,5.427 v1(9.605,5.427) ; 9.619,5.696 9.91,5.987 9.91,6.261 ; v1(9.735,8.542) 10.371,8.542 11.161,7.751 11.199,7.751 ; 9.911,6.262 9.911,6.463 11.199,7.751 ; R17.1@12.35,6.318 12.375,6.343 13.697,6.343 13.922,6.569 15.118,6.569 15.366,6.321 15.366,3.908 15.795,3.479 C17.2@16.747,3.479 16.747,3.429 16.455,3.137 L1.1@16.455,2.397 ; R17.1@12.491,6.459 11.199,7.751 ; DD2.8@13.955,11.235 14.18,11.235 14.23,11.285 C26.2@14.23,12.928 ; v1(14.082,13.61) 14.097,13.595 C26.2@14.097,13.028 ; L1.1@16.411,2.317 16.798,1.93 v1(16.98,1.93) ; v1(21.58,1.556) 21.974,1.556 22.552,2.135 22.821,2.135 R12.1@22.821,2.328 ; R3.2@23.855,9.78 23.763,9.78 23.663,9.88 23.663,12.311 23.412,12.562 23.412,12.709 23.91,13.207 R13.2@24.801,13.207
+5V_IN: FU1.1 VD1.C XP1.1 | length 5.3
  Top w0.18: XP1.1@-0.038,15.278 XP1.1@0,15.24
  Top w1: FU1.1@-2.54,15.278 XP1.1@-0.038,15.278
  Bot w0.18: XP1.1@-0.115,15.355 XP1.1@0,15.24
  Bot w0.8: VD1.C@-2.72,15.355 XP1.1@-0.115,15.355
